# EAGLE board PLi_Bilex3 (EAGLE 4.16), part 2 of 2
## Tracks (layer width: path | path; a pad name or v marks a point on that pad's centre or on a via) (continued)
N$15 (continued)
  Bottom 0.406: S5.2 71.05,18.98 arc-45 71.22,19.05 78.64,19.05 arc-45 78.81,18.98 S5.1 80.87,16.92 arc-45 80.94,16.74 D9.2
N$16
  Bottom 0.406: S6.1 92.78,18.98 arc45 92.61,19.05 85.19,19.05 arc45 85.02,18.98 S6.2 82.98,16.94 arc45 82.9,16.76 D9.1
N$17
  Top 0.356: IC1.8 61.28,81.6 61.28,99.27 arc45 61.2,99.45 58.42,102.23 I2C.4
  Bottom 0.356: I2C.4 R26.1
N$18
  Top 0.813: X3.1 R22.2 104.14,65.09 103.82,65.41 L1.2
N$19
  Bottom 0.406: S4.2 57.08,24.06 arc-45 57.26,24.13 64.67,24.13 arc-45 64.84,24.06 S4.1 67.87,21.03 arc-45 67.94,20.85 67.94,15.98 arc45 68.02,15.8 70.45,13.37 arc-45 70.52,13.19 D8.1
N$20
  Top 0.356: IC1.7 63.5,100.54 arc45 63.43,100.72 62.94,101.21 arc45 62.76,101.28 60.75,101.28 arc-45 60.57,101.36 59.76,102.16 arc-45 59.69,102.34 I2C.3
  Bottom 0.356: I2C.3 R25.1
N$21
  Bottom 0.356: K3.1 93.79,102.87 Q1.3
  Bottom 0.406: 89.53,102.55 K3.3 | R1.1 84.35,97.79 arc45 84.53,97.86 89.22,102.55 89.53,102.55 | 89.53,102.55 K3.1
N$22
  Top 0.61: -0.32,-0.32 -0.32,110.81 119.7,110.81 119.7,-0.32 -0.32,-0.32
N$23  (via drill 0.51 pad 1.02)
  Top 0.356: v68.58,73.98 66.43,71.83 arc45 66.36,71.65 66.36,66.36 IC1.24
  Bottom 0.356: K4.3 K4.1 108.88,88.46 arc45 108.7,88.38 102.31,81.99 arc45 102.23,81.81 102.23,78.84 arc-45 102.16,78.67 100.72,77.23 arc-45 100.54,77.15 83.61,77.15 arc-45 83.43,77.23 83.26,77.4 arc45 83.08,77.47 78.21,77.47 arc45 78.03,77.4 76.59,75.96 arc-45 76.41,75.88 69,75.88 arc45 68.82,75.81 68.65,75.64 arc45 68.58,75.46 v68.58,73.98
N$24
  Bottom 0.406: R24.2 97.16,106.36 99.27,106.36 arc-45 99.45,106.29 X6.1
N$25
  Bottom 0.356: C15.1 20.32,46.04 IC3.1
N$26
  Top 0.356: R16.2 63.5,54.29 C10.1
N$27
  Bottom 0.356: IC3.3 25.4,46.04 C3.2
N$28  (via drill 0.51 pad 1.02)
  Top 0.406: O1.4 138.43,36.73 arc-45 138.5,36.9 v139.7,38.1 | v139.7,41.91 137.23,44.38 arc-45 137.16,44.55 137.16,51.33 arc-45 137.23,51.51 139.63,53.9 arc45 139.7,54.08 139.7,59.59 arc45 139.63,59.76 138.5,60.89 arc-45 138.43,61.06 X7.8
  Bottom 0.406: R28.2 v139.7,38.1 D2.3 139.7,36.83 | R28.2 v139.7,41.91 | R28.2
N$29
  Bottom 0.406: 139.7,55.88 R8P.1 | R7P.2 137.16,55.88 139.7,55.88 | 139.7,55.88 140.9,57.08 arc45 140.97,57.26 IC8.2
N$30
  Bottom 0.406: R2.2 152.72,52.49 arc-45 152.64,52.31 152.47,52.14 arc45 152.4,51.97 152.4,41.7 arc-45 152.33,41.52 151.45,40.64 IC6.2 150.81,40.32 150.81,39.05 150.65,38.89 R27.1
N$31
  Bottom 0.406: D2.2 140.68,34.59 | 140.68,34.59 140.68,34.61 | 140.68,34.59 143.75,31.51 arc45 143.93,31.43 147.41,31.43 arc45 147.59,31.51 148.59,32.51 IC6.6 C25.1
N$32
  Bottom 0.406: 150.5,55.88 R6P.2 | R5P.2 147.32,53.34 148.17,53.34 arc45 148.35,53.41 148.83,53.9 arc45 148.91,54.08 148.91,55.14 arc-45 148.98,55.32 149.47,55.81 arc-45 149.65,55.88 150.5,55.88 | 150.5,55.88 150.5,56.73 arc-45 150.57,56.91 151.06,57.39 arc45 151.13,57.57 IC7.2
N$33
  Bottom 0.406: R32.2 148.59,48.26 IC7.6 150.42,52.63 arc45 150.5,52.81 R6P.1
N$34
  Top 0.406: X7.9 137.16,61.06 arc45 137.23,60.89 138.36,59.76 arc-45 138.43,59.59 IC8.3 138.43,55.98 arc-45 138.36,55.81 132.15,49.6 arc45 132.08,49.42 132.08,43.28 arc-45 132.01,43.11 130.88,41.98 arc45 130.81,41.8 IC4.2
N$35
  Top 0.406: X7.7 139.7,65.62 arc45 139.63,65.8 139.14,66.28 arc45 138.96,66.36 135.68,66.36 arc45 135.5,66.28 130.88,61.67 arc45 130.81,61.49 R29.3
  Bottom 0.406: 133.03,55.88 134.3,55.88 R3P.2 | 133.03,55.88 131.84,57.08 arc45 131.66,57.15 R29.3 | R4P.2 IC4.3 128.27,41.8 arc-45 128.34,41.98 129.47,43.11 arc45 129.54,43.28 129.54,47.52 arc-45 129.61,47.7 132.96,51.04 arc45 133.03,51.22 133.03,55.88
N$36
  Bottom 0.406: R27.2 150.5,36.83 148.59,36.83 C25.2
N$37
  Bottom 0.406: 144.78,53.34 R2P.2 | R1P.2 142.24,53.34 144.78,53.34 | 144.78,53.34 144.78,43.92 arc45 144.85,43.74 145.66,42.94 arc45 145.84,42.86 146.9,42.86 arc-45 147.08,42.79 148.59,41.27 IC6.3
N$38
  Bottom 0.406: R1P.1 142.24,58.95 arc45 142.17,59.13 141.36,59.93 arc45 141.18,60.01 128.69,60.01 arc45 128.51,59.93 R30.3 127.64,55.24 R34.2
N$39
  Bottom 0.406: 125.73,53.34 R30.2 | M2.11 128.27,47.52 arc45 128.2,47.7 125.8,50.09 arc-45 125.73,50.27 R30.1 125.73,53.34 | R34.1 127.64,53.34 125.73,53.34
N$40
  Bottom 0.406: M2.9 133.67,46.04 133.67,51.65 arc-45 133.74,51.83 134.23,52.31 arc45 134.3,52.49 R3P.1
N$41
  Bottom 0.406: D2.1 138.71,34.57 135.65,31.51 arc-45 135.47,31.43 129.65,31.43 arc-45 129.47,31.51 128.27,32.7 IC4.6
N$42
  Top 0.406: R31.1 O1.1
N$43
  Top 0.406: IC5.8 O1.2
N$44
  Bottom 0.406: C27.1 M2.2 151.13,48.26 R32.1
N$45  (via drill 0.51 pad 1.02)
  Top 0.406: M2.1 153.67,45.09 152.16,43.57 arc-45 151.98,43.5 141.07,43.5 arc-45 140.9,43.57 139.77,44.69 arc-45 139.7,44.87 v139.7,47.94
  Bottom 0.406: M2.1 C26.1 | v139.7,47.94 139.7,49.21 R33.1
N$46
  Top 0.406: M2.17 IC5.3
N$47
  Top 0.406: M2.18 139.63,3.74 arc45 139.7,3.92 IC5.6
N$48
  Top 0.356: IC5.4 137.16,7.83 arc-45 137.23,8.01 137.4,8.18 arc-45 137.58,8.26 138.43,8.26 | 138.43,8.26 141.5,8.26 arc45 141.68,8.33 142.48,9.13 arc45 142.56,9.31 142.56,17.78 | 142.56,17.78 142.56,19.05 | 142.56,19.05 142.56,20.32 | 142.56,20.32 142.56,21.59 | 142.56,21.59 142.56,22.86 R35.1 | 142.56,17.78 R39.1 | 142.56,19.05 R38.1 | 142.56,20.32 R37.1 | 142.56,21.59 R36.1 | 138.43,8.26 IC5.5
N$49  (via drill 0.51 pad 1.02)
  Top 0.356: 139.7,12.06 IC5.9 139.7,13.97 | 139.7,13.97 v139.7,16.51 | IC5.10 138.43,13.72 arc-90 138.68,13.97 139.7,13.97
  Bottom 0.356: v139.7,16.51 147.25,24.06 arc-45 147.43,24.13 X2.9
N$50
  Top 0.406: M2.3 148.59,46.25 arc-45 148.66,46.43 152.33,50.09 arc45 152.4,50.27 152.4,51.97 arc45 152.33,52.14 149.93,54.54 arc45 149.75,54.61 147.43,54.61 arc-45 147.25,54.68 144.85,57.08 arc-45 144.78,57.26 144.78,60.85 arc-45 144.85,61.03 X7.2
N$51  (via drill 2.18 pad 5.08)
  other vias: 125.73,3.81
N$52  (via drill 2.18 pad 5.08)
  other vias: 153.67,3.81
N$53  (via drill 2.18 pad 5.08)
  other vias: 153.67,64.77
N$54  (via drill 2.18 pad 5.08)
  other vias: 125.73,64.77
N$55
  Top 0.61: 121.6,-0.32 121.6,68.9 157.8,68.9 157.8,-0.32 121.6,-0.32
N$56  (via drill 0.51 pad 1.02)
  Top 0.356: 134.62,6.03 IC5.2 v134.62,8.57
  Bottom 0.356: v134.62,8.57 142.48,16.44 arc-45 142.66,16.51 X2.3
N$57
  Bottom 0.356: X2.10 152.29,25.4 arc-45 152.47,25.33 152.96,24.84 arc-45 153.03,24.66 153.03,11.54 arc-45 152.96,11.36 146.44,4.84 arc-45 146.26,4.76 143.3,4.76 arc45 143.12,4.69 M2.19
N$58
  Top 0.356: R35.2 X2.8
N$59
  Top 0.356: R36.2 X2.7
N$60
  Top 0.356: R37.2 X2.6
N$61
  Top 0.356: R38.2 X2.5
N$62
  Top 0.356: R39.2 X2.4
N$63
  Top 0.356: IC9.18 185.42,24.66 arc-45 185.49,24.84 189.16,28.5 arc45 189.23,28.68 189.23,29.61 arc45 189.16,29.79 188.03,30.91 arc-45 187.96,31.09 IC11.18
N$64  (via drill 0.51 pad 1.02)
  Top 0.356: 180.34,28.57 178.83,27.06 arc-45 178.65,26.99 168.59,26.99 v168.28,26.67
  Top 0.406: 180.34,28.57 IC9.5
  Bottom 0.356: C30.1 v168.28,26.67 164.57,26.67 arc-45 164.39,26.74 163.27,27.87 arc-45 163.19,28.05 Q2.2 163.19,29.84 163.51,30.16 Q3.2
N$65  (via drill 0.51 pad 1.02)
  Top 0.356: IC9.4 182.88,28.68 arc-45 182.81,28.5 179.78,25.47 arc-45 179.6,25.4 170.28,25.4 arc45 170.11,25.33 169.3,24.52 arc-45 169.12,24.45 v168.28,24.45
  Bottom 0.356: C31.1 v168.28,24.45 163.39,24.45 Q2.1 163.19,23.5 163.51,23.18 Q3.1
N$66
  Bottom 0.356: O2.3 174.75,7.62 | 176.02,6.35 R40.2
  Bottom 0.406: 174.75,7.62 176.02,6.35
N$67  (via drill 0.51 pad 1.02)
  Top 0.356: v180.34,18.29 179.14,19.48 arc-45 179.07,19.66 179.07,22.75 arc45 179,22.93 v177.8,24.13
  Top 0.406: IC9.7 IC9.8
  Bottom 0.356: O3.5 v180.34,18.29 180.97,18.92 181.51,18.92 | v177.8,24.13 177.8,26.57 arc45 177.73,26.74 IC9.7
  Bottom 0.406: 181.51,18.92 R41.2
N$68
  Bottom 0.356: R42.2 O3.3
N$69
  Bottom 0.356: C36.2 189.87,27.2 arc-45 189.94,27.38 190.43,27.87 arc45 190.5,28.05 IC9.1
N$71
  Bottom 0.356: O4.3 R44.1
N$72
  Top 0.406: IC11.1 I1.1
N$73
  Top 0.406: IC11.3 I2.1
N$74
  Top 0.406: IC11.5 I3.1
N$75
  Top 0.406: IC11.7 I4.1
N$76
  Top 0.356: IC12.5 168.91,43.18
  Top 0.406: 168.91,43.18 168.91,43.71 arc-45 168.98,43.89 170.11,45.01 arc45 170.18,45.19 I9.1
N$77
  Top 0.356: IC12.8 I11.1
N$78
  Bottom 0.356: R46.1 173.51,36.35 R45.2
N$79
  Top 0.61: 159.72,-0.3 193.34,-0.3 193.34,48.56 159.72,48.56 159.72,-0.3
N$80
  Top 0.356: LPT.1 132.1,79.99 arc-45 132.03,80.17 X8.1 132.03,86.62 arc45 131.96,86.8 129.61,89.14 arc-45 129.54,89.32 129.54,91.33 arc-45 129.61,91.51 132.64,94.54 arc-45 132.82,94.61 158.01,94.61 arc45 158.19,94.69 159.95,96.45 arc45 160.02,96.62 160.02,99.69 | 160.02,99.69 164.36,99.69 arc-45 164.54,99.62 IC13.10 | R50.1 160.02,99.69
N$81
  Top 0.356: LPT.3 134.69,79.94 arc-45 134.62,80.11 134.62,81.81 arc-45 134.69,81.99 134.72,82.02 arc45 134.8,82.2 X8.2 134.8,86.18 IC14.2
  Bottom 0.356: IC14.2 R51.1
N$82
  Top 0.356: LPT.5 137.23,79.94 arc-45 137.16,80.11 137.16,81.81 arc-45 137.23,81.99 137.47,82.22 arc45 137.54,82.4 X8.3 137.54,85.98 IC14.3
  Bottom 0.356: IC14.3 R52.1
N$83
  Top 0.356: LPT.7 139.77,79.94 arc-45 139.7,80.11 139.7,81.81 arc-45 139.77,81.99 140.24,82.45 arc45 140.31,82.63 X8.4 140.31,85.75 IC14.4
  Bottom 0.356: IC14.4 R53.1
N$84
  Top 0.356: LPT.9 142.31,79.94 arc-45 142.24,80.11 142.24,81.81 arc-45 142.31,81.99 143,82.68 arc45 143.08,82.86 X8.5 142.88,85.72 IC14.5
  Bottom 0.356: IC14.5 R54.1
N$85
  Top 0.356: LPT.11 144.85,79.94 arc-45 144.78,80.11 144.78,81.74 145.75,82.7 arc45 145.82,82.88 X8.6 145.41,85.72 144.78,86.36 | 144.78,86.36 IC14.6 | 144.78,86.36 144.87,86.27
  Bottom 0.356: IC14.6 R55.1
N$86
  Top 0.356: LPT.19 157.41,79.94 arc45 157.48,80.11 157.48,81.81 arc45 157.41,81.99 156.94,82.45 arc-45 156.87,82.63 X8.10 156.87,85.75 158.99,87.87 arc-45 159.17,87.95 166.58,87.95 arc45 166.76,88.02 IC13.6
N$87
  Top 0.356: IC14.19 130.81,98.95 arc-45 130.88,99.13 134.55,102.8 arc45 134.62,102.97 134.62,104.67 arc-45 134.69,104.85 135.18,105.34 arc-45 135.36,105.41 147.22,105.41 arc45 147.39,105.48 SPI.12 149.79,107.88 arc-45 149.97,107.95 155.15,107.95 arc-45 155.33,107.88 157.72,105.48 arc-45 157.8,105.31 157.8,103.29 arc45 157.87,103.11 158.36,102.63 arc45 158.54,102.55 166.58,102.55 arc-45 166.76,102.48 IC13.8
N$88
  Bottom 0.356: IC13.3 IC13.12 161.29,95.25 R48.1
N$89
  Top 0.356: LPT.17 154.87,79.94 arc45 154.94,80.11 154.94,81.81 arc45 154.87,81.99 154.18,82.68 arc-45 154.1,82.86 X8.9 153.67,85.72 149.22,90.17 IC14.9
  Bottom 0.356: IC14.9 R57.1
N$90
  Bottom 0.356: 158.75,95.25 C46.1 | 158.75,95.25 R48.2 | IC13.13 158.75,95.25
N$91
  Top 0.356: LPT.13 147.39,79.94 arc-45 147.32,80.11 147.32,81.52 arc-45 147.39,81.7 148.52,82.82 arc45 148.59,83 X8.7 147.96,85.72 IC14.7
  Bottom 0.356: IC14.7 R56.1
N$92
  Top 0.356: LPT.15 152.33,79.94 arc45 152.4,80.11 152.4,81.63 arc45 152.33,81.81 151.43,82.7 arc-45 151.36,82.88 X8.8
  Bottom 0.356: R49.2 IC13.1 155.04,90.17 arc45 154.87,90.1 151.43,86.66 arc45 151.36,86.48 X8.8
N$93
  Top 0.356: IC13.11 159.46,93.42 arc-45 159.28,93.34 149.33,93.34 arc45 149.15,93.27 IC14.8
N$94
  Top 0.356: IC14.18 133.35,98.95 arc-45 133.42,99.13 SPI.3
N$95
  Top 0.356: IC14.17 135.89,98.95 arc-45 135.96,99.13 SPI.5
N$96
  Top 0.356: IC14.16 138.43,98.95 arc-45 138.5,99.13 SPI.7
N$97
  Top 0.356: IC14.15 140.97,98.95 arc-45 141.04,99.13 SPI.9
N$98
  Top 0.356: IC14.14 143.51,98.95 arc-45 143.58,99.13 SPI.11
N$99
  Top 0.356: SPI.13 146.12,99.13 arc45 146.05,98.95 IC14.13
N$100
  Top 0.356: IC14.11 151.13,99.59 arc-45 151.2,99.77 153.6,102.16 arc45 153.67,102.34 SPI.15
N$101
  Top 0.356: 154.94,101.6 165,101.6 arc-45 165.17,101.53 167.57,99.13 arc-45 167.64,98.95 167.64,94.08 arc-45 167.57,93.91 IC13.4 | 154.94,101.6 154.94,105.31 arc45 154.87,105.48 SPI.16 | R58.1 154.94,99.69 154.94,101.6
N$102
  Top 0.356: IC14.12 148.59,98.95 arc-45 148.66,99.13 152.33,102.8 arc45 152.4,102.97 152.4,105.31 arc45 152.33,105.48 SPI.14
N$103
  Top 0.61: 175.58,110.81 121.6,110.81 121.6,74.61 175.58,74.61 175.58,110.81
N$104
  Top 0.406: IC15.7 175.26,60.96 RTS.1
N$105  (via drill 0.51 pad 1.02)
  Top 0.356: IC15.14 v170.81,55.88
  Bottom 0.356: v170.81,55.88 171.13,55.56 175.47,55.56 arc-45 175.65,55.49 TXD.1
N$106
  Top 0.406: IC15.8 RXD.1
N$107  (via drill 0.51 pad 1.02)
  Top 0.356: IC15.4 v172.72,57.15
  Bottom 0.356: v172.72,57.15 173.99,57.15 C51.1
N$108  (via drill 0.51 pad 1.02)
  Top 0.356: IC15.5 v172.72,58.42
  Bottom 0.356: v172.72,58.42 172.93,58.42 arc45 173.11,58.49 173.43,58.82 arc-45 173.61,58.89 C51.2
N$109  (via drill 0.51 pad 1.02)
  Top 0.356: v171.77,53.02 171.77,55.14 arc-45 171.84,55.32 172.33,55.81 arc-45 172.51,55.88 IC15.3
  Bottom 0.356: C50.2 172.09,53.34 v171.77,53.02
N$110
  Top 0.61: 159.72,50.49 159.72,68.89 178.1,68.89 178.1,50.49 159.72,50.49
N$111
  Bottom 0.356: MOSI1.1 162.8,58.66 arc-45 162.98,58.74 IC16.1
N$112
  Bottom 0.356: IC16.2 161.61,59.37 MISO1.1
N$113
  Bottom 0.356: IC16.3 162.98,60.01 arc-45 162.8,60.08 161.36,61.52 arc-45 161.29,61.7 CLK.1
N$114
  Bottom 0.356: IC16.4 163.3,60.64 arc-45 163.12,60.72 162.63,61.2 arc-45 162.56,61.38 162.56,63.4 arc45 162.49,63.57 CS.1
N$115
  Bottom 0.356: IC16.9 169.54,63.18 169.54,64.77 | 169.54,64.77 C55.1 | 169.54,64.77 170.39,64.77 arc45 170.57,64.84 171.45,65.72 Q4.1@1
N$116
  Bottom 0.356: 168.28,64.77 168.28,62.97 arc45 168.35,62.79 168.52,62.62 arc45 168.7,62.55 IC16.10 | 168.28,64.77 C54.1 | 168.28,64.77 167.43,64.77 arc-45 167.25,64.84 166.37,65.72 Q4.2@1
N$117  (via drill 0.51 pad 1.02)
  Top 0.356: v171.45,61.91 170.25,60.72 arc45 170.18,60.54 170.18,58.84 arc-45 170.11,58.66 169.94,58.49 arc-45 169.76,58.42 IC15.12
  Bottom 0.356: v171.45,61.91 IC16.11
N$118  (via drill 0.51 pad 1.02)
  Top 0.356: v167,60.96 IC15.10
  Bottom 0.356: v167,60.96 167.32,60.64 IC16.13
N$119  (via drill 0.51 pad 1.02)
  Top 0.406: v167,59.69 IC15.11
  Bottom 0.406: IC16.15 167.32,59.37 v167,59.69
N$120  (via drill 0.51 pad 1.02)
  Top 0.356: v171.45,60.01 172.65,61.2 arc45 172.72,61.38 172.72,62.44 arc45 172.65,62.62 172.48,62.79 arc45 172.3,62.87 169.65,62.87 arc45 169.47,62.79 168.91,62.23 IC15.9
  Bottom 0.356: IC16.14 v171.45,60.01
N$121
  Bottom 0.356: IC16.6 163.62,61.91 arc-45 163.44,61.99 163.27,62.16 arc-45 163.19,62.34 163.19,65.3 arc45 163.12,65.48 IRQ.1
N$122
  Bottom 0.356: IC16.7 165.63,62.55 arc-45 165.81,62.47 165.98,62.3 arc-45 166.05,62.12 166.05,58.52 arc-45 165.98,58.35 164.86,57.22 arc-45 164.68,57.15 163.94,57.15 arc45 163.76,57.08 SHDN.1
N$123  (via drill 0.51 pad 1.02)
  Top 0.356: v175.58,53.34 IC15.1
  Bottom 0.356: C50.1 v175.58,53.34
N$124
  Top 0.356: R64.2 190.18,91.44 187.96,93.66 IC17.3
  Bottom 0.356: 190.5,86.36 D4.3
  Bottom 0.406: R64.2 190.5,86.36 190.5,85.83 arc-45 190.43,85.65 188.03,83.26 arc45 187.96,83.08 R65.1
N$126
  Top 0.406: R66.2 186.62,92.64 arc45 186.69,92.81 186.69,99.91 arc-45 186.76,100.09 187.96,101.28 IC17.6 187.64,101.92 187.64,105.09 X9.2
  Bottom 0.356: R66.2 185.42,92.08 186.62,93.27 arc45 186.69,93.45 186.69,94.83 arc-45 186.76,95.01 187.16,95.4 C64.2
N$127
  Top 0.61: UD+.1 R64.1
  Bottom 0.61: UD+.1 R64.1
N$128
  Top 0.61: UD-.1 R63.1
  Bottom 0.61: UD-.1 R63.1
N$131
  Top 0.356: R63.2 182.88,91.76 185.1,93.98 IC17.2
  Bottom 0.356: C64.1 185.42,95.57 IC17.2 | 185.42,85.07 185.4,85.09 185.1,85.09 D3.3
  Bottom 0.406: R66.1 185.42,85.07 184.81,85.07 182.95,86.92 arc-45 182.88,87.1 R63.2
N$132
  Top 0.406: O6.3 186.69,66.02 arc45 186.76,65.84 187.76,64.84 arc45 187.94,64.77 P4.1
N$133
  Top 0.356: 186.69,60.33 O6.4
  Top 0.406: P8.1 185.19,62.23 arc-45 185.37,62.16 186.69,60.83 186.69,60.33 186.69,57.51 arc45 186.76,57.33 187.25,56.84 arc45 187.43,56.77 C59.2
N$134
  Top 0.356: R61.2 187.96,68.07 190.9,68.07 arc-45 191.08,68 P5.1
N$135
  Top 0.406: P7.1 187.89,61.03 arc-45 187.96,60.85 O6.5 187.96,58.17 R60.1
N$136
  Bottom 0.406: P1.1 191.77,57.78 186.64,62.92 arc-45 186.56,63.1 O5.4 186.56,66.95 arc-45 186.64,67.13 187.12,67.62 arc-45 187.3,67.69 C58.2
N$137
  Bottom 0.406: P2.1 187.91,63.55 arc-45 187.83,63.73 O5.5 187.83,66.42 R59.1
N$138
  Bottom 0.356: O5.6 189.1,63.86 arc45 189.18,63.68 190.55,62.3 arc45 190.73,62.23 P3.1
  Bottom 0.406: 189.1,66.42 O5.6 | 189.1,66.42 R59.2 | C58.1 189.1,67.69 189.1,66.42
N$139
  Top 0.406: P6.1 184.15,66.78 arc45 184.22,66.6 189.16,61.67 arc-45 189.23,61.49 O6.6 189.23,58.17 | 189.23,58.17 R60.2 | C59.1 189.23,56.77 189.23,58.17
N$140
  Bottom 0.406: P9.1 187.98,59.69 arc-45 188.16,59.62 189.03,58.75 arc-45 189.1,58.57 O5.1
N$141
  Top 0.813: 193.45,55.47 182.47,55.47 182.47,68.99 193.45,68.99 193.45,55.47
N$142
  Top 0.356: R61.1 189.23,66.27 O6.1
N$143
  Bottom 0.356: P10.1 184.61,56.69 arc45 184.79,56.62 R62.1
N$144
  Bottom 0.356: O5.3 186.56,58.17 187.83,58.17 R62.2
N$145
  Bottom 0.406: R67.2 186.69,104.03 arc45 186.62,104.21 186.13,104.7 arc-45 186.06,104.88 X9.3
N$146
  Bottom 0.406: R68.2 183.68,104.83 arc-45 183.75,105.01 184.15,105.41 X9.4
N$147  (via drill 0.51 pad 1.02)
  Top 0.406: IC17.4 190.5,97.69 arc45 190.43,97.86 v188.59,99.69
  Bottom 0.356: IC17.4 190.5,93.34 189.3,92.15 arc45 189.23,91.97 189.23,88.05 arc-45 189.16,87.87 188.67,87.39 arc45 188.59,87.21 188.59,85.72 188.33,85.46 arc-45 188.15,85.39 D4.2 187.35,85.39 186.13,86.6 arc45 185.95,86.68 185.21,86.68 arc-45 185.03,86.75 184.13,87.65 D3.2
  Bottom 0.406: v188.59,99.69 188.06,99.69 arc45 187.89,99.62 187.4,99.13 arc-45 187.22,99.06 186.69,99.06 R67.1 | C62.2 189.87,95.57 190.5,95.57 | 190.5,95.57 191.13,95.57 C63.2 | IC17.4 190.5,95.57
N$148
  Top 0.61: 180.03,75.89 180.03,110.8 193.34,110.8 193.34,75.89 180.03,75.89
N$149
  Bottom 0.356: 184.15,100.33 183.51,100.33 183.27,100.09 arc45 183.2,99.91 183.2,96.31 arc45 183.27,96.13 184.08,95.32 arc-45 184.15,95.14 184.15,90.28 arc45 184.22,90.1 186.09,88.23 D3.1 186.3,87.63 187.15,87.63 D4.1
  Bottom 0.406: 185.42,100.33 184.15,100.33 C60.1 | R68.1 185.42,103.5 IC17.7 185.42,100.33 | 185.42,100.33 C61.1
P00  (via drill 0.51 pad 1.02)
  Top 0.356: v76.83,46.35 81.21,50.73 arc45 81.28,50.91 81.28,64.03 arc-45 81.35,64.21 82.48,65.33 arc45 82.55,65.51 82.55,66.57 arc45 82.48,66.75 81.35,67.87 arc-45 81.28,68.05 IC1.36 | v17.78,52.07 15.31,54.54 arc-45 15.24,54.72 15.24,77.36 arc45 15.17,77.54 v14.61,78.11 14.04,78.67 arc-45 13.97,78.84 v13.97,90.17
  Bottom 0.356: v17.78,52.07 18.98,50.87 arc45 19.16,50.8 22.44,50.8 arc-45 22.62,50.73 23.74,49.6 arc45 23.92,49.53 30.69,49.53 arc-45 30.87,49.46 34.22,46.11 arc45 34.4,46.04 76.41,46.04 arc45 76.59,46.11 v76.83,46.35 | v14.61,78.11 15.17,77.54 arc45 15.35,77.47 19.58,77.47 arc-45 19.76,77.4 20.95,76.2 IC2.15 | R14.1 PORT0.3 v13.97,90.17
P01  (via drill 0.51 pad 1.02)
  Top 0.356: IC1.37 78.74,68.05 arc45 78.81,67.87 79.94,66.75 arc-45 80.01,66.57 v80.01,56.2 | 16.51,76.2 IC2.14 | v18.1,55.56 16.58,57.08 arc-45 16.51,57.26 16.51,76.2 | 16.51,76.2 16.51,87.84 arc45 16.44,88.02 v15.56,88.9
  Bottom 0.356: v18.1,55.56 18.34,55.32 arc45 18.52,55.24 72.92,55.24 arc45 73.1,55.32 73.9,56.12 arc-45 74.08,56.2 v80.01,56.2 | R13.1 PORT0.4 v15.56,88.9
P02  (via drill 0.51 pad 1.02)
  Top 0.356: v17.14,54.61 15.95,55.81 arc-45 15.88,55.98 15.88,79.06 | v83.82,55.56 84.06,55.81 arc45 84.14,55.98 84.14,69.11 arc45 84.06,69.29 82.31,71.05 arc45 82.13,71.12 IC1.38 | 15.88,79.06 v15.56,79.06 | 15.88,79.06 15.88,86.57 arc45 15.8,86.75 v14.92,87.63
  Bottom 0.356: v17.14,54.61 73.24,54.61 arc45 73.42,54.68 73.9,55.17 arc-45 74.08,55.24 83.4,55.24 arc45 83.58,55.32 v83.82,55.56 | v15.56,79.06 15.88,78.74 IC2.12 | R12.1 PORT0.5 v14.92,87.63
P03  (via drill 0.51 pad 1.02)
  Top 0.356: IC1.40 81.92,73.66 84.06,75.81 arc45 84.14,75.99 v84.14,90.17 | v20.32,87.63 20.32,82.66 arc45 20.39,82.48 IC2.11
  Bottom 0.356: v84.14,90.17 83.58,90.73 arc45 83.4,90.81 29.32,90.81 arc45 29.14,90.73 26.11,87.7 arc-45 25.93,87.63 v20.32,87.63 19.44,86.75 arc-45 19.26,86.68 7.94,86.68 PORT0.6 R11.1
P3A0
  Bottom 0.356: RX*.2 M1.2 101.53,53.27 arc-45 101.7,53.34 PORT3.3
P3A1
  Bottom 0.356: PORT3.4 100.44,54.61 arc45 100.26,54.54 M1.3 TX*.2
  Bottom 0.406: TX*.2 93.34,52.07
P3A2
  Bottom 0.356: PORT3.5 99.17,55.88 arc45 98.99,55.81 M1.4 INT0*.2
  Bottom 0.406: INT0*.2 93.34,54.61
P3A3
  Bottom 0.356: INT1*.2 M1.5 PORT3.6
P04  (via drill 0.51 pad 1.02)
  Top 0.356: v80.33,89.53 80.64,89.22 80.64,83.92 arc45 80.72,83.75 82.48,81.99 arc-45 82.55,81.81 82.55,77.58 arc-45 82.48,77.4 IC1.42 | v21.59,86.68 IC2.9
  Bottom 0.356: v80.33,89.53 79.77,90.1 arc45 79.59,90.17 29.95,90.17 arc45 29.77,90.1 26.43,86.75 arc-45 26.25,86.68 v21.59,86.68 20.74,86.68 arc45 20.56,86.6 20.08,86.12 arc-45 19.9,86.04 9.31,86.04 arc45 9.13,85.97 8.33,85.16 arc-45 8.15,85.09 PORT0.7 R10.1
  Bottom 0.406: R10.1 3.81,85.09
P05
  Bottom 0.356: IC1.44 65.51,78.74 arc45 65.33,78.67 64.21,77.54 arc-45 64.03,77.47 50.27,77.47 arc-45 50.09,77.54 47.7,79.94 arc45 47.52,80.01 41.06,80.01 arc45 40.88,79.94 39.76,78.81 arc-45 39.58,78.74 36.62,78.74 arc-45 36.44,78.81 35.63,79.62 arc-45 35.56,79.8 35.56,81.81 arc45 35.49,81.99 35,82.48 arc45 34.82,82.55 28.68,82.55 arc45 28.5,82.48 27.3,81.28 IC2.6 26.04,81.28 24.84,82.48 arc45 24.66,82.55 20.95,82.55 20.08,83.43 arc45 19.9,83.5 7.94,83.5 PORT0.8 R9.1
P06  (via drill 0.51 pad 1.02)
  Top 0.356: v79.06,89.22 79.94,88.34 arc-45 80.01,88.16 80.01,80.75 arc45 80.08,80.57 81.28,79.38 IC1.45 | v14.92,82.55 v14.92,85.09
  Bottom 0.356: v79.06,89.22 78.74,89.53 30.59,89.53 arc45 30.41,89.46 26.67,85.72 | 26.67,85.72 IC2.5 | v14.92,85.09 19.9,85.09 arc45 20.08,85.16 20.56,85.65 arc-45 20.74,85.72 26.67,85.72 | R8.1 PORT0.9 v14.92,82.55
P07  (via drill 0.51 pad 1.02)
  Top 0.356: v72.39,88.58 72.39,83.29 arc45 72.46,83.11 73.66,81.92 IC1.52 | PORT0.10 9.13,82.79 arc45 9.21,82.97 v9.21,84.45
  Bottom 0.356: v72.39,88.58 72.07,88.9 31.22,88.9 arc45 31.04,88.83 29.28,87.07 arc45 29.21,86.89 IC2.3 28.57,83.82 27.38,82.62 arc-45 27.2,82.55 26.14,82.55 arc-45 25.96,82.62 25.47,83.11 arc-45 25.4,83.29 25.4,84.35 arc45 25.33,84.53 24.84,85.02 arc45 24.66,85.09 21.06,85.09 arc45 20.88,85.02 20.08,84.21 arc-45 19.9,84.14 9.63,84.14 arc-45 9.45,84.21 v9.21,84.45 | R7.1 PORT0.10
  Bottom 0.406: R7.1 3.81,81.28
P10  (via drill 0.51 pad 1.02)
  Top 0.356: v36.51,69.85 36.51,78.95 arc-45 36.59,79.13 v37.15,79.69
  Bottom 0.356: IC1.47 78.11,83.82 76.91,82.62 arc-45 76.73,82.55 70.59,82.55 arc45 70.41,82.48 69.92,81.99 arc45 69.85,81.81 69.85,80.75 arc-45 69.78,80.57 69.29,80.08 arc-45 69.11,80.01 48.68,80.01 arc-45 48.5,80.08 46.11,82.48 arc45 45.93,82.55 38.84,82.55 arc45 38.66,82.48 38.17,81.99 arc45 38.1,81.81 38.1,80.75 arc-45 38.03,80.57 v37.15,79.69 | v36.51,69.85 36.27,69.61 arc-45 36.09,69.53 23.28,69.53 arc-45 23.1,69.61 IC2.19 21.06,71.12 arc-45 20.88,71.19 19.76,72.32 arc45 19.58,72.39 18.52,72.39 arc45 18.34,72.32 17.22,71.19 arc-45 17.04,71.12 PORT1.3
P11  (via drill 0.51 pad 1.02)
  Top 0.356: IC1.48 78.11,81.28 73.73,76.91 arc45 73.66,76.73 73.66,72.18 arc-45 73.59,72 v73.03,71.44
  Bottom 0.356: v73.03,71.44 67.73,71.44 arc-45 67.55,71.51 66.75,72.32 arc45 66.57,72.39 60.43,72.39 arc-45 60.25,72.46 59.45,73.27 arc45 59.27,73.34 48.68,73.34 arc45 48.5,73.27 47.7,72.46 arc-45 47.52,72.39 41.38,72.39 arc45 41.2,72.32 37.86,68.97 arc-45 37.68,68.9 21.91,68.9 IC2.21 20.39,69.78 arc45 20.21,69.85 PORT1.4
P12  (via drill 0.51 pad 1.02)
  Top 0.356: v91.76,45.72 91.76,82.23 v91.44,82.55 | v20.32,49.85 19.12,51.04 arc-45 19.05,51.22 19.05,56.09 arc45 18.98,56.27 17.22,58.03 arc-45 17.14,58.21 17.14,64.03 arc-45 17.22,64.21 IC2.22
  Bottom 0.356: v91.44,82.55 88.97,85.02 arc45 88.8,85.09 77.58,85.09 arc45 77.4,85.02 IC1.49 | v20.32,49.85 22.44,49.85 arc-45 22.62,49.77 23.42,48.97 arc45 23.6,48.9 30.38,48.9 arc-45 30.55,48.82 33.9,45.48 arc45 34.08,45.4 85.3,45.4 arc45 85.48,45.48 85.65,45.65 arc-45 85.83,45.72 v91.76,45.72 | IC2.22 16.58,68.51 arc45 16.41,68.58 PORT1.5
P13  (via drill 0.51 pad 1.02)
  Top 0.356: IC1.50 76.2,81.92 75,83.11 arc-45 74.93,83.29 v74.93,86.04 | v47.31,78.11 v47.31,87.31 | IC2.23 21.59,66.57 arc-45 21.66,66.75 22.79,67.87 arc45 22.86,68.05 22.86,71.65 arc-45 22.93,71.83 26.6,75.49 arc45 26.67,75.67 v26.67,76.52
  Bottom 0.356: v47.31,87.31 58.63,87.31 arc-45 58.81,87.24 59.62,86.43 arc45 59.8,86.36 74.61,86.36 v74.93,86.04 | v47.31,78.11 46.75,77.54 arc-45 46.57,77.47 27.62,77.47 v26.67,76.52 | PORT1.6 15.13,67.31 arc-45 15.31,67.24 17.71,64.84 arc45 17.89,64.77 20.21,64.77 arc45 20.39,64.84 IC2.23
P14  (via drill 0.51 pad 1.02)
  Top 0.356: v68.26,68.9 68.79,68.9 arc45 68.97,68.97 72.95,72.95 arc45 73.03,73.13 73.03,77.36 arc-45 73.1,77.54 74.86,79.3 arc45 74.93,79.48 74.93,81.81 arc45 74.86,81.99 73.66,83.19 IC1.51
  Bottom 0.356: v68.26,68.9 66.75,67.38 arc-45 66.57,67.31 41.38,67.31 arc45 41.2,67.24 40.71,66.75 arc45 40.64,66.57 40.64,65.83 arc-45 40.57,65.65 38.49,63.57 arc-45 38.31,63.5 IC2.25 20.39,62.3 arc-45 20.21,62.23 17.89,62.23 arc-45 17.71,62.3 14.04,65.97 arc45 13.87,66.04 PORT1.7
P15  (via drill 0.51 pad 1.02)
  Top 0.356: IC1.4 68.58,80.96 64.84,77.23 arc45 64.77,77.05 64.77,75.67 arc-45 64.7,75.49 64.21,75 arc-45 64.03,74.93 62.97,74.93 arc45 62.79,74.86 62.3,74.37 arc45 62.23,74.19 62.23,73.13 arc-45 62.16,72.95 61.67,72.46 arc-45 61.49,72.39 58.84,72.39 arc45 58.66,72.32 55.32,68.97 arc45 55.24,68.79 55.24,59.16 arc-45 55.17,58.98 v54.93,58.74
  Bottom 0.356: v54.93,58.74 54.61,58.42 43.92,58.42 arc-45 43.74,58.49 42.62,59.62 arc45 42.44,59.69 22.96,59.69 arc45 22.79,59.62 IC2.27 20.39,59.62 arc45 20.21,59.69 18.2,59.69 arc-45 18.02,59.76 13.09,64.7 arc45 12.91,64.77 PORT1.8
P16  (via drill 0.51 pad 1.02)
  Top 0.356: v19.37,58.74 IC2.28 21.59,61.49 arc-45 21.66,61.67 23.42,63.43 arc45 23.5,63.6 23.5,71.33 arc-45 23.57,71.51 27.87,75.81 arc45 27.94,75.99 27.94,85.3 arc-45 28.01,85.48 28.5,85.97 arc-45 28.68,86.04 v31.75,86.04
  Bottom 0.356: v31.75,86.04 31.99,85.8 arc45 32.17,85.72 56.73,85.72 arc-45 56.91,85.65 57.39,85.16 arc45 57.57,85.09 64.67,85.09 arc-45 64.84,85.02 IC1.5 | PORT1.9 13.23,63.5 arc-45 13.41,63.43 18.02,58.81 arc45 18.2,58.74 v19.37,58.74
P17  (via drill 0.51 pad 1.02)
  Top 0.356: v30.48,85.09 30.48,77.58 arc-45 30.41,77.4 24.2,71.19 arc45 24.13,71.02 24.13,62.97 arc-45 24.06,62.79 22.93,61.67 arc45 22.86,61.49 22.86,60.43 arc45 22.93,60.25 24.06,59.13 arc-45 24.13,58.95 IC2.29
  Bottom 0.356: IC1.6 65.41,81.28 64.21,82.48 arc45 64.03,82.55 62.97,82.55 arc-45 62.79,82.62 61.35,84.06 arc45 61.17,84.14 57.57,84.14 arc-45 57.39,84.21 56.59,85.02 arc45 56.41,85.09 v30.48,85.09 | PORT1.10 13.55,62.23 arc-45 13.73,62.16 18.66,57.22 arc45 18.84,57.15 22.75,57.15 arc45 22.93,57.22 IC2.29
P30  (via drill 0.51 pad 1.02)
  Top 0.356: IC1.20 60.96,53.13 arc45 61.03,52.95 v65.09,48.9
  Bottom 0.356: RX*.1 M1.9 86.75,48.65 arc-45 86.57,48.58 65.51,48.58 arc-45 65.33,48.65 v65.09,48.9 | IC2.34 29.84,60.96 31.36,62.47 arc-45 31.54,62.55 38.95,62.55 arc45 39.13,62.62 41.2,64.7 arc-45 41.38,64.77 44.98,64.77 arc45 45.16,64.84 45.96,65.65 arc-45 46.14,65.72 50.7,65.72 arc-45 50.87,65.65 51.04,65.48 arc45 51.22,65.41 52.92,65.41 arc45 53.1,65.48 54.22,66.6 arc-45 54.4,66.67 60.22,66.67 arc-45 60.4,66.6 IC1.20
P31  (via drill 0.51 pad 1.02)
  Top 0.356: v73.98,57.15 73.98,63.08 arc45 73.9,63.26 IC1.29
  Bottom 0.356: TX*.1 M1.8 86.43,53.27 arc-45 86.36,53.45 86.36,54.51 arc45 86.29,54.68 83.89,57.08 arc45 83.72,57.15 v73.98,57.15 71.54,57.15 arc45 71.36,57.08 70.88,56.59 arc-45 70.7,56.52 38.84,56.52 arc-45 38.66,56.59 IC2.39
P32  (via drill 0.51 pad 1.02)
  Top 0.356: v38.42,53.02 38.17,53.27 arc-45 38.1,53.45 38.1,58.95 arc45 38.03,59.13 36.9,60.25 arc-45 36.83,60.43 IC2.40 | v88.58,50.8 88.83,51.04 arc45 88.9,51.22 88.9,54.61 | 88.9,54.61 88.9,57.68 arc45 88.83,57.86 87.07,59.62 arc-45 87,59.8 87,66.89 arc-45 87.07,67.07 v87.31,67.31 | 88.9,54.61 M1.7
  Bottom 0.356: M1.7 INT0*.1 | v38.42,53.02 39.3,52.14 arc45 39.48,52.07 44.98,52.07 arc45 45.16,52.14 45.65,52.63 arc-45 45.83,52.7 84.98,52.7 arc-45 85.16,52.63 86.92,50.87 arc45 87.1,50.8 v88.58,50.8 | v87.31,67.31 75.03,67.31 arc45 74.86,67.24 IC1.30
P33  (via drill 0.51 pad 1.02)
  Top 0.356: v76.2,58.1 IC1.31
  Bottom 0.356: INT1*.1 M1.6 86.75,58.03 arc45 86.57,58.1 v76.2,58.1 71.54,58.1 arc45 71.36,58.03 70.56,57.22 arc-45 70.38,57.15 40.74,57.15 arc-45 40.57,57.22 IC2.41
P34  (via drill 0.51 pad 1.02)
  Top 0.356: v73.03,61.59 v73.03,59.05
  Bottom 0.356: IC1.32 76.2,65.41 75,64.21 arc45 74.93,64.03 74.93,62.97 arc-45 74.86,62.79 73.73,61.67 arc-45 73.56,61.59 v73.03,61.59 72.18,61.59 arc45 72,61.52 70.88,60.4 arc-45 70.7,60.33 52.49,60.33 arc-45 52.31,60.4 51.83,60.89 arc45 51.65,60.96 46.46,60.96 arc-45 46.28,61.03 45.16,62.16 arc45 44.98,62.23 40.74,62.23 arc45 40.57,62.16 IC2.42 | v73.03,59.05 101.5,59.05 arc-45 101.67,58.98 102.16,58.49 arc45 102.34,58.42 PORT3.7
P35
  Bottom 0.356: IC2.43 42.47,57.86 arc45 42.65,57.78 70.06,57.78 arc45 70.24,57.86 72.32,59.93 arc-45 72.5,60.01 78.74,60.01 | 97.79,60.96 QG1*.8 | 78.74,60.01 97.05,60.01 arc45 97.23,60.08 97.79,60.64 97.79,60.96 | 97.79,60.96 T1*.1 | 78.74,60.01 IC1.33
P36
  Bottom 0.356: IC2.45 42.55,60.96 44.38,59.13 arc45 44.55,59.05 51.65,59.05 arc45 51.83,59.13 52.31,59.62 arc-45 52.49,59.69 71.02,59.69 arc45 71.19,59.76 72,60.57 arc-45 72.18,60.64 75.14,60.64 arc45 75.32,60.72 77.4,62.79 arc45 77.47,62.97 77.47,64.67 arc-45 77.54,64.84 IC1.35 79.94,64.84 arc45 80.11,64.77 81.81,64.77 arc45 81.99,64.84 83.43,66.28 arc-45 83.61,66.36 87.84,66.36 arc45 88.02,66.43 88.83,67.24 arc-45 89,67.31 97.05,67.31 arc-45 97.23,67.24 98.99,65.48 arc-45 99.06,65.3 99.06,64.24 arc45 99.13,64.06 102.8,60.4 arc45 102.97,60.33 110.07,60.33 arc45 110.25,60.4 110.73,60.89 arc-45 110.91,60.96 PORT3.9
P37  (via drill 0.51 pad 1.02)
  Top 0.356: IC2.47 41.91,62.97 arc45 41.98,62.79 43.11,61.67 arc-45 43.18,61.49 43.18,60.43 arc45 43.25,60.25 44.38,59.13 arc-45 44.45,58.95 v44.45,53.02 | v77.47,53.66 77.47,69.11 arc-45 77.54,69.29 78.67,70.41 arc45 78.74,70.59 IC1.39
  Bottom 0.356: v44.45,53.02 44.69,53.27 arc-45 44.87,53.34 77.05,53.34 arc45 77.23,53.41 v77.47,53.66 | PORT3.10 110.59,62.23 arc45 110.42,62.16 109.29,61.03 arc-45 109.11,60.96 103.61,60.96 arc-45 103.43,61.03 100.09,64.38 arc-45 100.01,64.56 100.01,65.62 arc45 99.94,65.8 97.55,68.19 arc45 97.37,68.26 83.61,68.26 arc-45 83.43,68.34 81.99,69.78 arc45 81.81,69.85 80.11,69.85 arc-45 79.94,69.92 IC1.39
P40  (via drill 0.51 pad 1.02)
  Top 0.356: IC1.1 v71.12,87.95 71.12,91.65 arc-45 71.19,91.83 79.94,100.57 arc45 80.01,100.75 PORT4.3 | v31.43,67.94 31.43,78.95 arc-45 31.51,79.13 32.95,80.57 arc45 33.02,80.75 v33.02,87.95 LCD4X20.6
  Bottom 0.356: v31.43,67.94 31.11,68.26 23.28,68.26 arc45 23.1,68.19 22.3,67.38 arc-45 22.12,67.31 20.43,67.31 arc-45 20.25,67.38 IC2.20 | v71.12,87.95 70.8,88.27 33.34,88.27 v33.02,87.95
P41  (via drill 0.51 pad 1.02)
  Top 0.356: IC1.2 71.12,81.92 69.92,83.11 arc-45 69.85,83.29 69.85,91.33 arc-45 69.92,91.51 78.67,100.26 arc45 78.74,100.44 PORT4.4 | v21.59,48.9 21.59,54.51 arc45 21.52,54.68 17.85,58.35 arc-45 17.78,58.52 17.78,62.12 arc-45 17.85,62.3 IC2.24 | v86.36,44.77 v86.36,78.74
  Bottom 0.356: v21.59,48.9 22.15,48.33 arc45 22.33,48.26 30.06,48.26 arc-45 30.24,48.19 33.58,44.84 arc45 33.76,44.77 36.83,44.77 | 36.83,44.77 v86.36,44.77 | v86.36,78.74 85.16,79.94 arc45 84.98,80.01 72.5,80.01 arc-45 72.32,80.08 IC1.2 | X4.1 X4.2 36.83,44.77
  Bottom 0.406: 40.32,10.16 69.53,10.16 | 40.32,10.16 D7.3 | D9.3 81.92,10.16 69.53,10.16 | 69.53,10.16 D8.3 | 40.32,10.16 30.59,10.16 arc-45 30.41,10.23 25.47,15.17 arc-45 25.4,15.35 25.4,25.3 arc-45 25.47,25.47 36.76,36.76 arc45 36.83,36.94 X4.1
P42  (via drill 0.51 pad 1.02)
  Top 0.356: IC1.3 68.58,91.02 arc-45 68.65,91.2 77.4,99.94 arc45 77.47,100.12 PORT4.5 | v58.42,86.04 58.98,85.48 arc-45 59.05,85.3 59.05,75.67 arc-45 58.98,75.49 51.51,68.02 arc45 51.44,67.84 51.44,42.65 arc45 51.51,42.47 X4.14 | LCD4X20.4 28.57,97.79 31.04,95.32 arc-45 31.11,95.14 v31.11,87.31 28.05,87.31 arc45 27.87,87.24 25.47,84.85 arc45 25.4,84.67 25.4,75.67 arc-45 25.33,75.49 22.3,72.46 arc-45 22.12,72.39 21.06,72.39 arc45 20.88,72.32 20.39,71.83 arc45 20.32,71.65 20.32,62.34 arc-45 20.25,62.16 IC2.26
  Bottom 0.356: IC1.3 66.75,85.65 arc45 66.57,85.72 58.74,85.72 v58.42,86.04 58.1,86.36 33.12,86.36 arc-45 32.95,86.43 32.14,87.24 arc45 31.96,87.31 v31.11,87.31 | X4.14 X4.13 | PORT4.5 R4.2
  Bottom 0.406: S6.3 S6.4 75.32,31.36 arc45 75.14,31.43 57.57,31.43 arc-45 57.39,31.51 52.14,36.76 arc-45 52.07,36.94 X4.13
P43  (via drill 0.51 pad 1.02)
  Top 0.356: IC1.9 64.7,82.48 arc45 64.77,82.66 v64.77,94.93 71.33,94.93 arc45 71.51,95.01 76.13,99.62 arc45 76.2,99.8 PORT4.6 | X4.12 50.73,43.11 arc45 50.8,43.28 50.8,60.01 | 50.8,60.01 v50.48,60.01 | 50.8,60.01 50.8,68.16 arc-45 50.87,68.34 58.35,75.81 arc45 58.42,75.99 58.42,81.92 v58.1,82.23
  Bottom 0.356: v50.48,60.01 45.51,60.01 arc-45 45.33,60.08 IC2.44 | X4.11 X4.12 | v58.1,82.23 58.42,82.55 61.49,82.55 arc-45 61.67,82.48 62.87,81.28 IC1.9 | v64.77,94.93 42.33,94.93 arc-45 42.15,95.01 40.71,96.45 arc45 40.53,96.52 32.49,96.52 arc-45 32.31,96.59 31.19,97.72 arc45 31.01,97.79 LCD4X20.5 | PORT4.6 R17.2
  Bottom 0.406: S5.3 S5.4 69.85,27.2 arc45 69.78,27.38 67.07,30.09 arc45 66.89,30.16 56.3,30.16 arc-45 56.12,30.24 49.6,36.76 arc-45 49.53,36.94 X4.11
P44  (via drill 0.51 pad 1.02)
  Top 0.356: 50.8,78.74 50.8,75.03 arc-45 50.73,74.86 49.92,74.05 arc45 49.85,73.87 v49.85,64.77 49.6,64.53 arc45 49.53,64.35 49.53,44.55 arc-45 49.46,44.38 X4.10 | 50.8,78.74 v51.12,78.74 | 50.8,78.74 50.8,93.24 arc-45 50.87,93.42 54.54,97.08 arc45 54.61,97.26 v54.61,101.28
  Bottom 0.356: v51.12,78.74 IC1.10 | X4.9 X4.10 | v49.85,64.77 46.14,64.77 arc45 45.96,64.7 44.77,63.5 IC2.46 | R18.2 PORT4.7 74.93,102.34 arc-45 74.86,102.16 74.37,101.67 arc-45 74.19,101.6 69.95,101.6 arc45 69.78,101.53 69.29,101.04 arc-45 69.11,100.97 54.93,100.97 v54.61,101.28 54.29,100.97 49.63,100.97 arc45 49.46,100.89 46.43,97.86 arc-45 46.25,97.79 LCD4X20.11
  Bottom 0.406: S4.3 S4.4 47.06,36.76 arc-45 46.99,36.94 X4.9
P45  (via drill 0.51 pad 1.02)
  Top 0.356: v54.29,68.26 54.29,68.79 arc-45 54.37,68.97 60.25,74.86 arc-45 60.43,74.93 61.49,74.93 arc45 61.67,75 62.16,75.49 arc45 62.23,75.67 62.23,77.36 arc-45 62.3,77.54 IC1.11 62.3,79.94 arc-45 62.23,80.11 v62.23,100.01 | v73.66,100.65 PORT4.8 | X4.8 44.45,43.71 arc-45 44.52,43.89 48.19,47.55 arc45 48.26,47.73 v48.26,68.26
  Bottom 0.356: IC2.50 44.98,68.58 arc-45 45.16,68.51 45.33,68.34 arc45 45.51,68.26 v48.26,68.26 v54.29,68.26 | v73.66,100.65 70.27,100.65 arc45 70.09,100.57 69.61,100.09 arc-45 69.43,100.01 v62.23,100.01 61.06,100.01 arc-45 60.89,100.09 60.72,100.26 arc45 60.54,100.33 50.91,100.33 arc45 50.73,100.26 LCD4X20.12 | X4.7 X4.8 | PORT4.8 R19.2
  Bottom 0.406: S3.2 64.84,18.98 arc45 64.67,19.05 57.26,19.05 arc45 57.08,18.98 S3.1 54.05,19.61 arc-45 53.98,19.79 53.98,27.52 arc45 53.9,27.7 44.52,37.07 arc-45 44.45,37.25 X4.7
P46  (via drill 0.51 pad 1.02)
  Top 0.356: IC2.53 42.55,71.12 43.74,72.32 arc-45 43.92,72.39 45.3,72.39 arc45 45.48,72.46 46.6,73.59 arc-45 46.78,73.66 v47.31,73.66 | v47.31,73.66 47.31,74.51 arc-45 47.38,74.69 49.46,76.76 arc45 49.53,76.94 49.53,95.14 arc-45 49.6,95.32 50.73,96.45 arc45 50.8,96.62 LCD4X20.13 | v47.31,73.66 47.31,67.73 arc45 47.38,67.55 47.55,67.38 arc-45 47.62,67.2 47.62,48.37 arc-45 47.55,48.19 41.98,42.62 arc45 41.91,42.44 X4.6 | v72.39,99.69 PORT4.9
  Bottom 0.356: v72.39,99.69 70.59,99.69 arc45 70.41,99.62 69.92,99.13 arc-45 69.75,99.06 60.75,99.06 arc-45 60.57,99.13 60.08,99.62 arc45 59.9,99.69 52.81,99.69 arc45 52.63,99.62 LCD4X20.13 | v47.31,73.66 47.55,73.9 arc-45 47.73,73.98 60.64,73.98 IC1.14 | 41.91,39.69 X4.6 | PORT4.9 R20.2
  Bottom 0.406: S2.3 S2.4 41.91,39.69 X4.5
P47  (via drill 0.51 pad 1.02)
  Top 0.356: v46.35,43.81 48.82,46.28 arc45 48.9,46.46 48.9,67.2 arc-45 48.97,67.38 49.14,67.55 arc45 49.21,67.73 v49.21,74.93 50.09,75.81 arc45 50.16,75.99 50.16,94.51 arc-45 50.24,94.69 LCD4X20.14 | v71.12,98.74 PORT4.10
  Bottom 0.356: IC2.57 43.11,75 arc45 43.28,74.93 v49.21,74.93 61.49,74.93 arc-45 61.67,74.86 62.79,73.73 arc45 62.97,73.66 IC1.15 | v71.12,98.74 70.88,98.5 arc-45 70.7,98.42 60.11,98.42 arc-45 59.93,98.5 59.45,98.99 arc45 59.27,99.06 54.72,99.06 arc45 54.54,98.99 LCD4X20.14 | X4.3 X4.4 39.37,42.76 arc-45 39.44,42.94 40.25,43.74 arc-45 40.43,43.81 v46.35,43.81 | PORT4.10 R21.2
  Bottom 0.406: S1.4 S1.3 39.3,24.06 arc45 39.37,24.23 X4.3
P50  (via drill 0.51 pad 1.02)
  Top 0.356: v34.61,87.31 34.29,87.63 34.29,98.32 arc45 34.22,98.5 33.09,99.62 arc45 32.91,99.69 28.05,99.69 arc-45 27.87,99.77 26.74,100.89 arc-45 26.67,101.07 PORT5.3 | v44.13,87.31 44.45,87 IC2.60
  Bottom 0.356: v34.61,87.31 v44.13,87.31
P51  (via drill 0.51 pad 1.02)
  Top 0.356: IC2.62 41.91,81.92 40.71,83.11 arc-45 40.64,83.29 v40.64,94.93 | v32.07,95.57 31.75,95.89 31.75,98.32 arc45 31.68,98.5 31.19,98.99 arc45 31.01,99.06 27.73,99.06 arc-45 27.55,99.13 25.47,101.21 arc-45 25.4,101.39 PORT5.4
  Bottom 0.356: v32.07,95.57 32.38,95.89 39.9,95.89 arc-45 40.08,95.81 40.64,95.25 v40.64,94.93
P52  (via drill 0.51 pad 1.02)
  Top 0.356: IC2.63 v39.37,94.93 | v29.84,94.93 29,94.93 arc-45 28.82,95.01 26.74,97.08 arc-45 26.67,97.26 26.67,98.95 arc45 26.6,99.13 24.2,101.53 arc-45 24.13,101.7 PORT5.5
  Bottom 0.356: v39.37,94.93 39.05,95.25 33.44,95.25 arc45 33.26,95.18 32.78,94.69 arc-45 32.6,94.61 30.27,94.61 arc-45 30.09,94.69 v29.84,94.93
P53
  Top 0.356: IC2.7 24.13,100.22 arc45 24.06,100.4 22.93,101.53 arc-45 22.86,101.7 PORT5.6
P54
  Top 0.356: IC2.8 22.93,82.48 arc-45 22.86,82.66 22.86,95.78 arc45 22.79,95.96 21.66,97.08 arc-45 21.59,97.26 PORT5.7
P55
  Top 0.356: IC2.10 19.05,101.18 arc-45 19.12,101.36 20.32,102.55 PORT5.8
P56
  Top 0.356: IC2.13 20.39,79.94 arc45 20.21,80.01 18.52,80.01 arc-45 18.34,80.08 17.85,80.57 arc-45 17.78,80.75 17.78,87.53 arc-45 17.85,87.7 18.34,88.19 arc45 18.41,88.37 18.41,101.5 arc-45 18.49,101.67 18.98,102.16 arc45 19.05,102.34 PORT5.9
P57
  Top 0.356: IC2.16 20.25,74.86 arc45 20.32,75.03 20.32,76.73 arc45 20.25,76.91 19.76,77.4 arc45 19.58,77.47 18.52,77.47 arc-45 18.34,77.54 17.22,78.67 arc-45 17.14,78.84 17.14,87.84 arc-45 17.22,88.02 17.71,88.51 arc45 17.78,88.69 PORT5.10
P60
  Top 0.356: IC2.54 45.3,73.66 arc45 45.48,73.73 48.82,77.08 arc45 48.9,77.26 48.9,95.78 arc-45 48.97,95.96 49.46,96.45 arc45 49.53,96.62 49.53,98.32 arc45 49.46,98.5 47.06,100.89 arc-45 46.99,101.07 PORT6.3
P61
  Top 0.356: IC2.55 42.55,73.66 43.74,74.86 arc-45 43.92,74.93 45.62,74.93 arc45 45.79,75 48.19,77.4 arc45 48.26,77.58 48.26,95.14 arc45 48.19,95.32 47.06,96.45 arc-45 46.99,96.62 46.99,98.64 arc45 46.92,98.82 45.79,99.94 arc-45 45.72,100.12 PORT6.4
P62
  Top 0.356: IC2.56 45.62,76.2 arc45 45.79,76.27 46.28,76.76 arc45 46.35,76.94 46.35,95.14 arc45 46.28,95.32 44.52,97.08 arc-45 44.45,97.26 PORT6.5
P63
  Top 0.356: IC2.58 45.65,79.94 arc45 45.72,80.11 45.72,94.51 arc45 45.65,94.69 43.25,97.08 arc-45 43.18,97.26 PORT6.6
P64
  Top 0.356: IC2.59 43.11,79.94 arc45 43.18,80.11 43.18,95.78 arc45 43.11,95.96 41.98,97.08 arc-45 41.91,97.26 PORT6.7
P65
  Top 0.356: IC2.61 41.91,95.78 arc45 41.84,95.96 40.71,97.08 arc-45 40.64,97.26 PORT6.8
P66
  Top 0.356: IC2.64 39.37,81.92 38.17,83.11 arc-45 38.1,83.29 38.1,95.14 arc-45 38.17,95.32 39.3,96.45 arc45 39.37,96.62 PORT6.9
P67
  Top 0.356: IC2.65 36.83,94.83 arc-45 36.9,95.01 38.03,96.13 arc45 38.1,96.31 PORT6.10
PGND
  Top 0.406: IC7.3 148.59,60.54 arc45 148.52,60.72 147.39,61.84 arc-45 147.32,62.02 147.32,62.76 arc45 147.25,62.94 146.76,63.43 arc45 146.58,63.5 143.62,63.5 arc-45 143.44,63.57 X7.5
  Bottom 0.406: R2.1 152.72,56.73 arc45 152.64,56.91 152.47,57.08 arc-45 152.4,57.26 152.4,58.95 arc45 152.33,59.13 151.84,59.62 arc45 151.66,59.69 149.97,59.69 arc45 149.79,59.62 IC7.3
PLFF
  Top 0.356: C11.2 66.04,59.05 63.5,59.05 | 63.5,59.05 IC1.21 | C10.2 63.5,59.05
  Top 0.406: C10.2 63.5,58.1
PSEN  (via drill 0.51 pad 1.02)
  Top 0.356: v33.02,56.52 33.02,61.49 arc-45 33.09,61.67 35.49,64.06 arc45 35.56,64.24 35.56,81.81 arc45 35.49,81.99 34.36,83.11 arc-45 34.29,83.29 IC2.67 | v72.07,56.2 72.07,62.12 arc-45 72.15,62.3 72.32,62.47 arc45 72.39,62.65 72.39,64.03 arc45 72.32,64.21 71.19,65.33 arc-45 71.12,65.51 IC1.28
  Bottom 0.356: R3.1 15.77,55.24 arc45 15.95,55.32 17.07,56.44 arc-45 17.25,56.52 v33.02,56.52 33.58,55.95 arc45 33.76,55.88 71.65,55.88 arc45 71.83,55.95 v72.07,56.2
R1IN  (via drill 0.51 pad 1.02)
  Top 0.356: IC15.13 v170.81,57.15
  Bottom 0.356: CTS.1 175.65,56.27 arc-45 175.47,56.2 172.19,56.2 arc-45 172.01,56.27 171.13,57.15 v170.81,57.15
R5P
  Bottom 0.305: 170.12,9.65 170.31,9.65 170.18,9.53 | O4.6 170.31,8.13 170.18,8.26
  Bottom 0.356: R26*.1 173.86,6.76 173.86,9.65
  Bottom 0.406: 181.61,9.65 O3.1 | 177.29,9.65 O2.1
  Bottom 0.508: M3.1 163.76,3.74 arc45 163.83,3.92 163.83,9.65 | 163.83,9.65 163.83,15.13 arc45 163.76,15.31 162.63,16.44 arc-45 162.56,16.61 M3.24 | C35.1 188.09,9.65 181.61,9.65 | 181.61,9.65 177.29,9.65 173.86,9.65 170.12,9.65 163.83,9.65 | 181.61,9.65 C37.1 | 170.18,9.53 170.18,8.26 R5P1.1
RGND  (via drill 0.51 pad 1.02)
  Top 0.406: v172.72,5.08 178.97,5.08 arc-45 179.14,5.01 180.27,3.88 arc-45 180.34,3.71 RGND.1
  Bottom 0.406: v172.72,5.08 172.72,6.75 arc-45 172.79,6.93 172.9,7.04 arc45 172.97,7.22 O4.4 | 188.09,4.32 188.09,4.29 | C37.2 181.61,4.32
  Bottom 0.508: 181.61,4.32 188.09,4.32 | 190.5,4.29 M3.12 | 190.5,4.29 M3.13 | 190.5,4.29 188.09,4.29 C35.2 | RGND.1 181.54,3.74 arc45 181.61,3.92 C37.2
RIN
  Bottom 0.356: IC3.2 24.06,43.25 arc45 24.23,43.18 30.38,43.18 arc-45 30.55,43.11 X5.2 X5.1
  Bottom 0.406: X5.1 27.94,35.56 25.47,33.09 arc-45 25.3,33.02 7.62,33.02 K2.2 K2.4
RSTN
  Top 0.356: IC3.5 27.94,53.23 arc45 27.87,53.41 25.47,55.81 arc-45 25.4,55.98 25.4,58.95 arc45 25.33,59.13 24.2,60.25 arc-45 24.13,60.43 IC2.30
RSTP  (via drill 0.51 pad 1.02)
  Top 0.356: v74.93,54.29 74.93,67.52 arc-45 75,67.7 77.4,70.09 arc45 77.47,70.27 77.47,74.83 arc-45 77.54,75 IC1.43
  Bottom 0.356: IC3.6 27.23,53.9 arc-45 27.41,53.98 74.51,53.98 arc45 74.69,54.05 v74.93,54.29
RX
  Bottom 0.356: O2.5 176.02,16.02 arc-45 176.1,16.2 176.46,16.56 arc45 176.53,16.74 176.53,18.69 arc-45 176.6,18.87 177.73,19.99 arc-45 177.91,20.07 178.2,20.07 arc45 178.38,20.14 179,20.75 arc45 179.07,20.93 179.07,22.12 arc-45 179.14,22.3 181.1,24.26 181.61,24.26 | 181.61,24.26 182.9,24.26 arc45 183.08,24.33 IC9.2 | 181.61,24.26 R43.1
SCK
  Bottom 0.406: R40.1 176.02,3.41 arc-45 175.95,3.23 MOSI.1
TX
  Bottom 0.356: IC9.3 184.78,29.21 178.51,22.93 arc-45 178.33,22.86 177.4,22.86 arc45 177.22,22.79 176.6,22.17 arc45 176.53,21.99 176.53,21.06 arc-45 176.46,20.88 175.97,20.39 arc-45 175.79,20.32 174.6,20.32 arc45 174.42,20.25 173.23,19.05 172.97,19.05 R44.2
UA-
  Bottom 0.406: 144.78,55.88 147.32,55.88 R5P.1 | R2P.1 144.78,55.88 | 144.78,55.88 144.78,58.95 arc45 144.71,59.13 143.27,60.57 arc45 143.09,60.64 142.66,60.64 arc-45 142.48,60.72 X7.6
UCAP
  Bottom 0.356: C9.1 65.72,69.85 62.34,69.85 arc45 62.16,69.78 IC1.18
USB0
  Bottom 0.356: K4.4 K4.2 113.87,87.07 arc-45 113.69,87 108.37,87 arc45 108.19,86.92 103.58,82.31 arc45 103.5,82.13 R5.1
USB1  (via drill 0.51 pad 1.02)
  Top 0.356: v69.53,74.93 68.05,74.93 arc45 67.87,74.86 67.7,74.69 arc45 67.63,74.51 67.63,74.08 arc-45 67.55,73.9 65.8,72.15 arc45 65.72,71.97 65.72,67.73 arc-45 65.65,67.55 64.84,66.75 arc45 64.77,66.57 64.77,65.51 arc45 64.84,65.33 65.97,64.21 arc-45 66.04,64.03 IC1.23
  Bottom 0.356: v69.53,74.93 82.13,74.93 arc45 82.31,75 83.43,76.13 arc-45 83.61,76.2 R6.1
USB2
  Bottom 0.356: R15.1 101.6,74.3 99.77,72.46 arc-45 99.59,72.39 78.21,72.39 arc45 78.03,72.32 77.54,71.83 arc45 77.47,71.65 77.47,69.64 arc-45 77.4,69.46 75.96,68.02 arc-45 75.78,67.94 73.77,67.94 arc45 73.59,67.87 72.46,66.75 arc45 72.39,66.57 72.39,65.51 arc-45 72.32,65.33 71.83,64.84 arc-45 71.65,64.77 65.51,64.77 arc-45 65.33,64.84 64.21,65.97 arc45 64.03,66.04 IC1.22
V+  (via drill 0.51 pad 1.02)
  Top 0.356: v172.72,54.61 IC15.2
  Bottom 0.356: C53.1 170.39,53.34 arc45 170.57,53.41 171.69,54.54 arc-45 171.87,54.61 v172.72,54.61
V-  (via drill 0.51 pad 1.02)
  Top 0.356: IC15.6 v172.72,59.69
  Bottom 0.356: v172.72,59.69 173.92,60.89 arc45 173.99,61.06 C52.1
VADJ  (via drill 0.51 pad 1.02)
  Top 0.356: v176.53,34.92 179.6,34.92 arc-45 179.78,34.85 180.27,34.36 arc-45 180.34,34.19 IC11.12 180.34,33.02
  Bottom 0.356: C43.1 v176.53,34.92 174.94,34.92 R46.2
VCC  (via drill 0.51 pad 1.02)
  Top 0.356: v170.18,54.61 170.18,53.76 arc-45 170.11,53.58 169.94,53.41 arc-45 169.76,53.34 IC15.16
  Bottom 0.356: 169.54,58.67 169.54,58.74 IC16.16
  Bottom 0.406: 169.54,54.61 v170.18,54.61 | 169.54,54.61 169.54,58.67 | 5P.1 163.83,54.61 | 163.83,54.61 165.1,54.61 | 165.1,54.61 169.54,54.61 | 165.1,54.61 C57.1 | 163.83,54.61 C56.1
VREF  (via drill 0.51 pad 1.02)
  Top 0.356: v177.8,33.66 178.33,33.66 arc-45 178.51,33.58 179.07,33.02
  Top 0.406: 179.07,33.02 IC11.11
  Bottom 0.356: C42.1 178.12,33.97 v177.8,33.66 R45.3
XTAL1  (via drill 0.51 pad 1.02)
  Top 0.356: v35.56,91.76 35.56,83.29 arc45 35.63,83.11 36.12,82.62 arc45 36.3,82.55 37.36,82.55 arc-45 37.54,82.48 38.03,81.99 arc-45 38.1,81.81 38.1,68.69 arc45 38.17,68.51 40.57,66.11 arc45 40.74,66.04 IC2.49 | v67.31,91.76 67.31,80.75 arc-45 67.24,80.57 63.5,76.83 IC1.13
  Top 0.406: Q1*.1 C2.1
  Bottom 0.356: v35.56,91.76 v67.31,91.76 92.84,91.76 | 92.84,91.76 Q1*.1 | 92.84,91.76 Q2*.2
XTAL2  (via drill 0.51 pad 1.02)
  Top 0.356: v52.39,66.36 52.39,67.84 arc-45 52.46,68.02 59.62,75.17 arc45 59.69,75.35 59.69,76.2 | 59.69,76.2 59.69,86.57 arc-45 59.76,86.75 v60.33,87.31 | 59.69,76.2 IC1.12
  Top 0.406: Q1*.2 C1.1
  Bottom 0.356: v60.33,87.31 60.64,87 90.38,87 arc-45 90.56,86.92 91.68,85.8 arc45 91.86,85.72 95.78,85.72 arc45 95.96,85.8 97.66,87.5 Q1*.2 Q2*.1 | IC2.48 44.69,66.28 arc-45 44.87,66.36 v52.39,66.36

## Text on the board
Top: SPI | USB | AT89C51ED2/31A | RESET | ESC | ENTER
Bottom: PLi2006 | PLi06
tPlace: 68
tNames: USB | PROG | RESET
Reference: 54 | 36
tDocu: 112mm | 120mm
